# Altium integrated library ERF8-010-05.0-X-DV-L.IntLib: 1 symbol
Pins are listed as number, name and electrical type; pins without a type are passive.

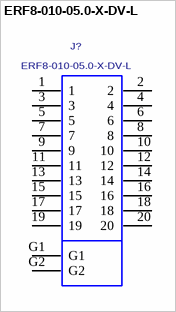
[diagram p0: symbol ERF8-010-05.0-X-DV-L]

## ERF8-010-05.0-X-DV-L
designator J?
0.8mm Edge Rate Socket Assembly, Double Vertical Row, 20 Pins.; MANUFACTURER: SAMTEC
footprint ERF8-010-05.0-X-DV-L
pins: 1, 2, 3, 4, 5, 6, 7, 8, 9, 10, 11, 12, 13, 14, 15, 16, 17, 18, 19, 20, G1, G2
